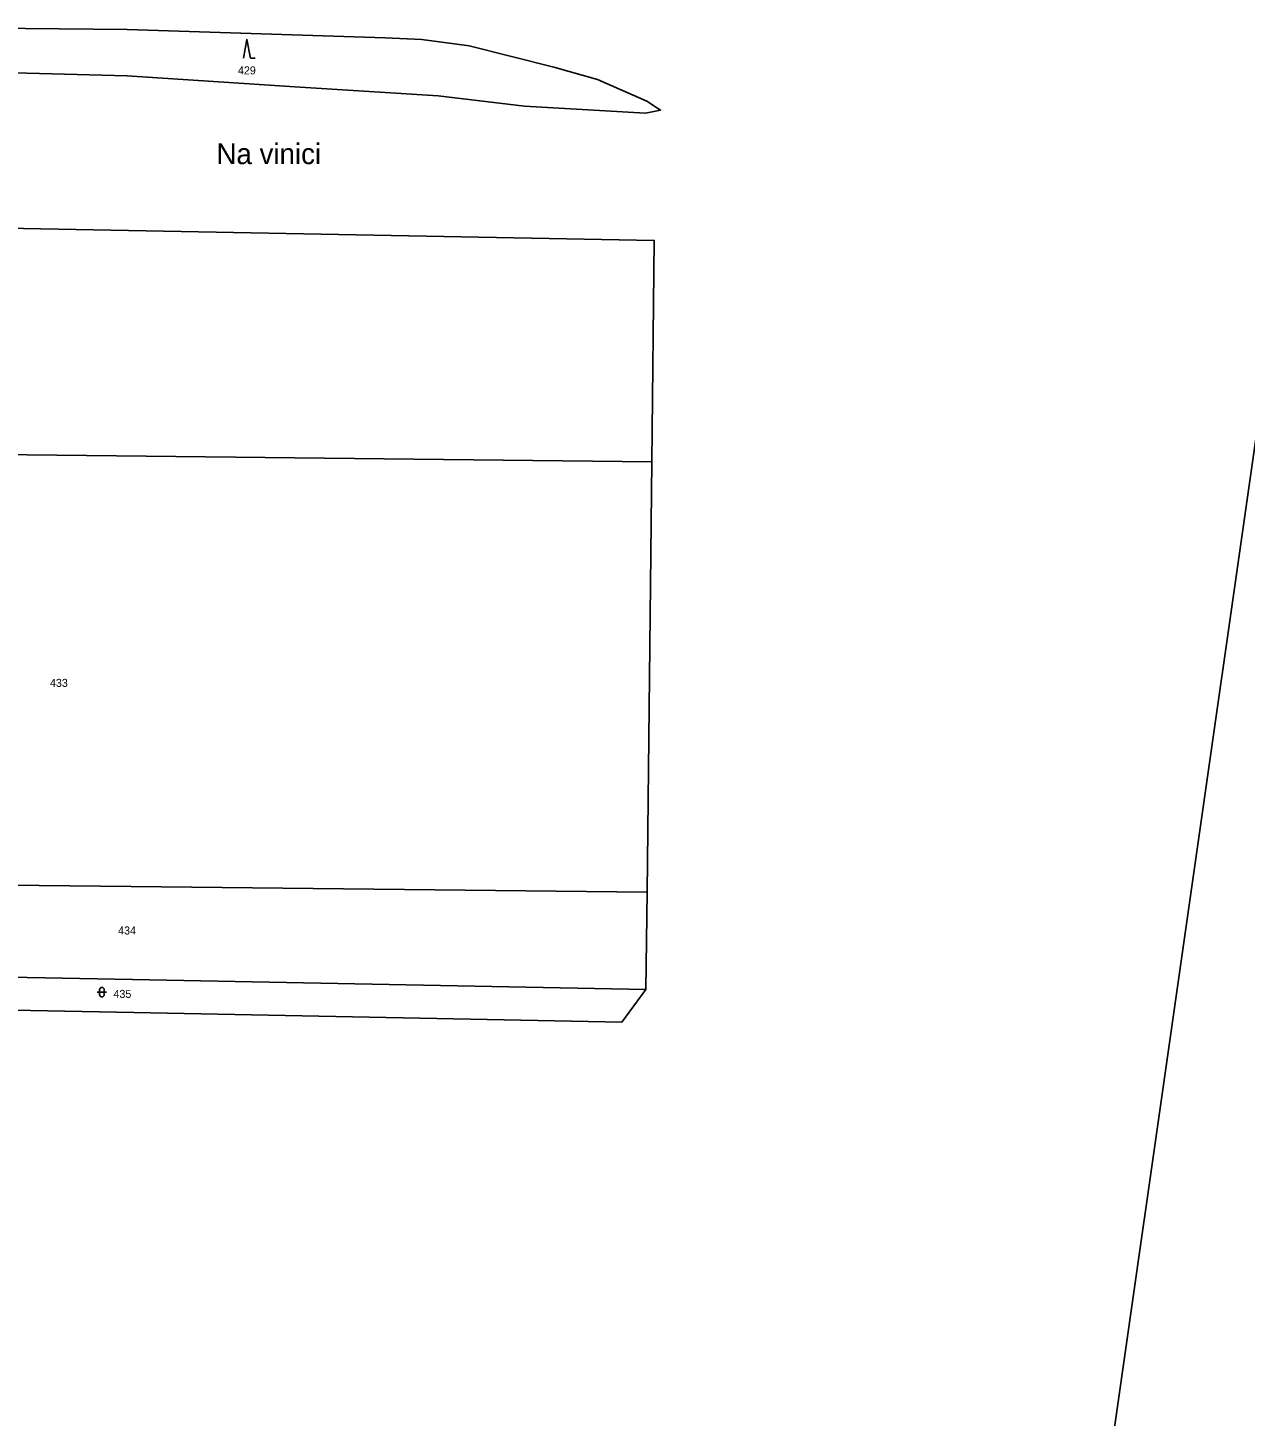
# Model space of a CAD drawing. Extents: x -769392 to -767038, y -1018329 to -1015269.
# Drawn here: x -768526.3 to -768267.7, y -1016085.5 to -1015790.5 of the extents above; entities that cross this region are included whole.
import ezdxf

# ---------------------------------------------------------------- set-up
doc = ezdxf.new("R2010")
doc.units = 0
doc.header["$LTSCALE"] = 0.68
for name, color, linetype, lineweight in [('1', 7, 'Continuous', 25), ('3', 7, 'Continuous', 25), ('7', 7, 'Continuous', 13)]:
    doc.layers.add(name, color=color, linetype=linetype, lineweight=lineweight)
doc.layers.add('2', color=7, linetype='Continuous')

msp = doc.modelspace()

# ---------------------------------------------------------------- linework, layer by layer
at = {"layer": '1'}
for p, q in [((-768393.76, -1015882.77), (-768394.77, -1015974.17)), ((-768394.77, -1015974.17), (-768395, -1015994.87))]:
    msp.add_line(p, q, dxfattribs=at)
msp.add_lwpolyline([(-768562.42, -1015798.46), (-768542.47, -1015799.78), (-768505.13, -1015800.77), (-768469.57, -1015803.07), (-768439.12, -1015804.99), (-768420.78, -1015807.18), (-768395.06, -1015808.66), (-768391.9, -1015808.02), (-768394.8, -1015806.1), (-768405.31, -1015801.53), (-768414.59, -1015798.93), (-768432.56, -1015794.35), (-768442.59, -1015793.04), (-768450.35, -1015792.69), (-768505.18, -1015790.92), (-768541.24, -1015790.54), (-768564.76, -1015791.31), (-768574.64, -1015792.9), (-768577.78, -1015795.16), (-768571.04, -1015796.95)], close=True, dxfattribs=at)
for points in [[(-768393.76, -1015882.77), (-768393.24, -1015835.72), (-768557.04, -1015832.59)], [(-768262.64, -1015858.01), (-768282.68, -1015998.29), (-768308.65, -1016180.07)], [(-768393.76, -1015882.77), (-768526.38, -1015881.3), (-768672.64, -1015879.68)], [(-768628.22, -1015971.61), (-768504.28, -1015972.97), (-768394.77, -1015974.17)], [(-768395, -1015994.87), (-768504.06, -1015992.76), (-768612.03, -1015990.68), (-768618.56, -1015989.11)], [(-768608.35, -1016002), (-768606.17, -1015997.79), (-768503.74, -1015999.77), (-768400.14, -1016001.77), (-768395, -1015994.87)]]:
    msp.add_lwpolyline(points, dxfattribs=at)
at = {"layer": '3'}
for p, q in [((-768478.99, -1015797.02), (-768477.994, -1015797.02)), ((-768511.541, -1015995.421), (-768509.539, -1015995.421)), ((-768511.041, -1015994.921), (-768511.041, -1015995.922)), ((-768510.039, -1015995.922), (-768510.039, -1015994.921))]:
    msp.add_line(p, q, dxfattribs=at)
msp.add_lwpolyline([(-768478.99, -1015797.02), (-768479.74, -1015793.02), (-768480.49, -1015797.02)], dxfattribs=at)
for centre, start, end in [((-768510.54, -1015994.9209), 0, 180), ((-768510.54, -1015995.9209), 180, 359.98789)]:
    msp.add_arc(centre, 0.5, start, end, dxfattribs=at)

# ---------------------------------------------------------------- texts
at = {"layer": '2'}
for s, p in [('429', (-768481.64, -1015800.445)), ('433', (-768521.56, -1015930.565)), ('434', (-768507.09, -1015983.165)), ('435', (-768508.07, -1015996.645))]:
    msp.add_text(s, height=1.7, dxfattribs=at).set_placement(p)
at = {"layer": '7'}
msp.add_text('Na vinici', height=4.4, dxfattribs=at).set_placement((-768486.21, -1015819.51))

doc.saveas('drawing.dxf')
